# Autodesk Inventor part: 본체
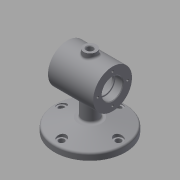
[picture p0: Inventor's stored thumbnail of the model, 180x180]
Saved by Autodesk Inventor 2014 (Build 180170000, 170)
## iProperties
Created: 2018-12
Part Number: 본체
Material: Generic
Document SubType Name: Modeling
Designer: kh
Density: 1 g/cm^3
Appearance: Default
Author: kh
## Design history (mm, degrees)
sketch "Sketch1"
  geometry: C1 r 55 at (0, 0); 1 further point
  constraints: 1 centre point, 1 coincident
  dimensions: "d0" = 110 diameter of C1
extrude "Extrusion1" new body sketch "Sketch1" distance "d1" = 10; taper "d2" = 0 deg
sketch "Sketch2"
  geometry: L1 (0, 0)-(0, 75); L2 (35, 75)-(-35, 75); L3 (-35, 91)-(-23, 91); L4 (-23, 91)-(-23, 89); L5 (-23, 89)-(-20, 89); L6 (-20, 89)-(-20, 100); L7 (-20, 100)-(20, 100); L8 (20, 100)-(20, 89); L9 (20, 89)-(23, 89); L10 (23, 89)-(23, 91); L11 (23, 91)-(35, 91); L12 (35, 91)-(35, 105); L13 (35, 105)-(-35, 105); L14 (-35, 105)-(-35, 91)
  constraints: 28 end point, 10 parallel, 2 perpendicular, 1 collinear, 1 midpoint, 1 vertical, 1 vertical alignment
  dimensions: "d3" = 75 distance of L1.end L1.start; "d4" = 70 distance of L2.start L2.end; "d5" = 12 distance of L3.start L3.end; "d6" = 3 distance of L4.end L5.end; "d7" = 40 distance of L6.end L7.end; "d8" = 3 distance of L8.end L9.end; "d9" = 12 distance of L10.end L11.end; "d10" = 32 diameter of L3 L2; "d11" = 28 diameter of L5 L2; "d12" = 50 diameter of L7 L2; "d13" = 28 diameter of L9 L2; "d14" = 32 diameter of L11 L2; "d15" = 60 diameter of L13 L2
revolve "Revolution1" sketch "Sketch2" stored, may be unused: angle "d16" = 90 deg
sketch "Sketch3"
  geometry: C1 r 12 at (0, 0); 1 further point
  constraints: 1 centre point, 1 coincident
  dimensions: "d17" = 24 diameter of C1
extrude "Extrusion2" join sketch "Sketch3" stored distance "d18" = 10; taper "d19" = 0 deg
sketch "Sketch4"
  geometry: L1 (55, 10)-(-55, 10) reference; L2 (-55, 0)-(55, 0) reference; L3 (-12, 10)-(-12, 45) reference; L4 (-55, 0)-(-55, 10) reference; L5 (-55, 10)-(-12, 21.522); L6 (12, 10)-(12, 45) reference; L7 (-12, 21.522)-(12, 21.522); 1 further point
  constraints: 4 end point, 2 point on line, 1 perpendicular
  dimensions: "d20" = 75 deg angle of L5 L4
  node "Projected Loop1"
workplane "Work Plane1"
sketch "Sketch5"
  geometry: C1 r 10 at (0, 0); 1 further point
  constraints: 1 centre point, 1 coincident
  dimensions: "d22" = 20 diameter of C1
extrude "Extrusion3" join sketch "Sketch5" stored distance "d23" = 10; taper "d24" = 0 deg
hole "Hole1" diameter "d27" = 10; stored, may be unused: countersink angle "d31" = 90 deg, drill point angle "d33" = 118 deg; dims "d25" = 10, "d26" = 10, "d28" = 6, "d29" = 4, "d30" = 2, "d32" = 8
fillet "Fillet1" dims "d34" = 3
fillet "Fillet2" dims "d35" = 0.3
chamfer "Chamfer1" distance "d36" = 1; stored, may be unused: second distance "d37" = 2, angle "d38" = 45 deg
sketch "Sketch6" dims "d39" = 46
  geometry: L1 (0, 0)-(23, 0); C1 r 17 at (0, 0) reference; 2 further points
  constraints: 2 coincident, 2 end point, 1 horizontal, 1 horizontal alignment, 2 other
hole "Hole2" sketch "Sketch6" at (23, 0) diameter "d40" = 3.459; stored, may be unused: countersink angle "d44" = 90 deg, drill point angle "d46" = 118 deg; dims "d41" = 8, "d42" = 4, "d43" = 2, "d45" = 10
pattern_circular "Circular Pattern1" dims angle "d48" = 360 deg
mirror "Mirror1"
workplane "Work Plane2"
sketch "Sketch7"
  geometry: L1 (-35, 30)-(35, 30) reference; L2 (-35, -30)-(-35, 30) reference; L3 (-22.743, 3.292)-(22.743, 3.292); L4 (22.743, 3.292)-(22.743, -3.292); L5 (22.743, -3.292)-(-22.743, -3.292); L6 (-22.743, -3.292)-(-22.743, 3.292); L7 (-22.743, 3.292)-(22.743, -3.292); L8 (0, 30)-(0, 0); 1 further point
  constraints: 4 end point, 2 midpoint, 1 parallel, 2 other
  dimensions: "d50" = 30 distance of L8.end L8.start; "d51" = 35 distance between parallel lines of L8 L2
emboss "Emboss1" sketch "Sketch7" dims "d52" = 0.5, "d53" = 0
workplane "Work Plane3"
sketch "Sketch8"
  geometry: C1 r 12 at (-12, 0) reference; 1 further point
sketch "Sketch9"
  geometry: C1 r 55 at (0, 0) reference; C2 r 55 at (0, 0); 1 further point
  constraints: 1 centre point, 1 coincident, 1 concentric
extrude "Extrusion4" join sketch "Sketch9" distance "d54" = 10; taper "d55" = -75 deg
fillet "Fillet3" dims "d56" = 3
sketch "Sketch10" dims "d57" = 88
  geometry: L1 (0, 0)-(0, -44); C1 r 4.5 at (0, -44); 1 further point
  constraints: 2 coincident, 2 end point, 1 centre point, 1 vertical, 1 vertical alignment, 2 other
  dimensions: "d58" = 9 diameter of C1
extrude "Extrusion5" cut sketch "Sketch10" distance "d59" = 10; taper "d60" = 0 deg
workplane "Work Plane4"
pattern_circular "Circular Pattern2" dims angle "d65" = 360 deg
fillet "Fillet4" dims "d67" = 3
fillet "Fillet5" dims "d68" = 3
chamfer "Chamfer2" distance "d69" = 1; stored, may be unused: second distance "d70" = 2, angle "d71" = 45 deg
fillet "Fillet6" dims "d72" = 3
sketch "Sketch12"
  geometry: C1 r 4.5 at (0, 0) reference; C2 r 4.5 at (0, 0) reference; C3 r 7 at (0, 0); 1 further point
  constraints: 1 centre point, 1 coincident
  dimensions: "d73" = 14 diameter of C3
extrude "Extrusion7" cut sketch "Sketch12" stored distance "d74" = 10; taper "d75" = 0 deg
pattern_circular "Circular Pattern3" dims angle "d77" = 360 deg
body "Solid1"
node "Projected Loop2"
node "Projected Loop3"
other parameters: "d21" = 112
